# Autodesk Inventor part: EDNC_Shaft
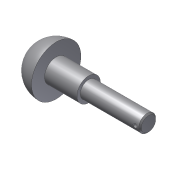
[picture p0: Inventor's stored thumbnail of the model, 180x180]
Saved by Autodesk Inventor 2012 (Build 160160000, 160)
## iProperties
Created: 2010-10
Part Number: EDNC_Shaft
Document SubType Name: Modeling
Designer: JSSONG
Density: 1 g/cm^3
Mass: 26.7233 g
Surface Area: 67.7439 cm^2
Volume: 26.7233 cm^3
Material: 기본값
Author: JSSONG
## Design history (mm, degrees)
sketch "스케치1"
  geometry: L1 (-19, 0)-(71, 0); L2 (71, 0)-(71, 6.5); L3 (71, 6.5)-(25, 6.5); L4 (25, 6.5)-(25, 9); L5 (25, 9)-(0, 9); L6 (0, 9)-(0, 19); A1 r 19 centre (0, 0) between (0, 19) and (-19, 0); 1 further point
  constraints: 12 end point, 4 parallel, 2 point on circle, 1 centre point, 1 coincident, 1 horizontal, 1 horizontal alignment, 1 perpendicular, 1 vertical alignment
  dimensions: "d0" = 90 distance of L1.start L1.end; "d1" = 19 radius of A1; "d2" = 13 diameter of L3 L1; "d3" = 18 diameter of L5 L1; "d4" = 25 distance of L4.end L5.end
revolve "회전1" sketch "스케치1" stored, may be unused: angle "d5" = 90 deg
node "작업 평면1"
sketch "스케치2"
  geometry: L1 (-23, 6.5)-(-23, -6.5) reference; 3 further points
  constraints: 1 horizontal alignment, 1 midpoint
  dimensions: "d6" = 4 distance from line of L1 point (-19, 0)
hole "Hole1" sketch "스케치2" at (-19, 0) diameter "d7" = 3; stored, may be unused: countersink angle "d11" = 90 deg, drill point angle "d13" = 118 deg; dims "d8" = 6, "d9" = 4, "d10" = 2, "d12" = 8
chamfer "모따기1" distance "d14" = 1; stored, may be unused: second distance "d15" = 2, angle "d16" = 45 deg
sketch "스케치3"
  geometry: C1 r 9 at (0, 0) reference; C2 r 19 at (0, 0) reference
node "솔리드1"
node "투영된 루프1"
